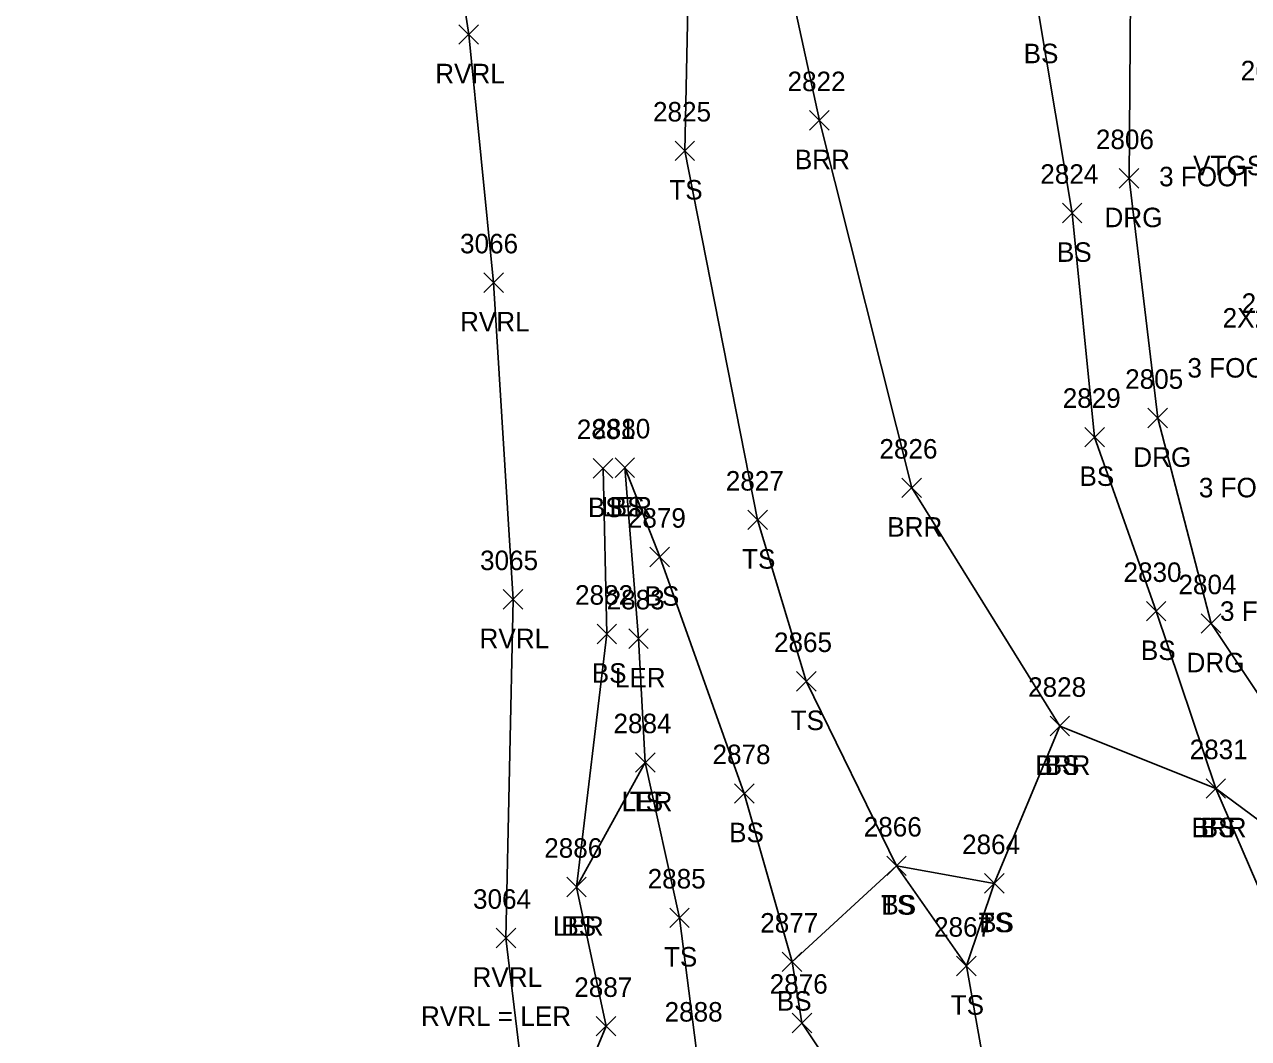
# Model space of a CAD drawing. Extents: x 1461855 to 1464118, y 556196 to 557441.
# Drawn here: x 1462198.6 to 1462324.1, y 556771.6 to 556875.5 of the extents above; entities that cross this region are included whole.
import ezdxf

# ---------------------------------------------------------------- set-up
doc = ezdxf.new("R2010")
doc.units = 0
for name, color, linetype in [('C_C', 7, 'Continuous'), ('L_A', 7, 'Continuous'), ('L_C', 7, 'Continuous'), ('L_I', 7, 'Continuous'), ('L_TIC', 7, 'Continuous'), ('LABL', 7, 'Continuous'), ('LARO', 7, 'Continuous'), ('LAWE', 7, 'Continuous'), ('LELB', 7, 'Continuous'), ('LSOGP', 7, 'Continuous'), ('R_A', 7, 'Continuous'), ('R_I', 7, 'Continuous'), ('R_TIC', 7, 'Continuous'), ('RDG', 7, 'Continuous')]:
    doc.layers.add(name, color=color, linetype=linetype)

msp = doc.modelspace()

# ---------------------------------------------------------------- linework, layer by layer
at = {"layer": 'L_TIC'}
for points in [[(1462243.13, 556873.5), (1462245.13, 556875.5)], [(1462245.13, 556873.5), (1462243.13, 556875.5)], [(1462279.07, 556864.7), (1462281.07, 556866.7)], [(1462281.07, 556864.7), (1462279.07, 556866.7)], [(1462265.28, 556861.59), (1462267.28, 556863.59)], [(1462267.28, 556861.59), (1462265.28, 556863.59)], [(1462304.98, 556855.21), (1462306.98, 556857.21)], [(1462306.98, 556855.21), (1462304.98, 556857.21)], [(1462245.68, 556848.08), (1462247.68, 556850.08)], [(1462247.68, 556848.08), (1462245.68, 556850.08)], [(1462307.29, 556832.25), (1462309.29, 556834.25)], [(1462309.29, 556832.25), (1462307.29, 556834.25)], [(1462256.9, 556829.05), (1462258.9, 556831.05)], [(1462258.9, 556829.05), (1462256.9, 556831.05)], [(1462259.14, 556829.12), (1462261.14, 556831.12)], [(1462261.14, 556829.12), (1462259.14, 556831.12)], [(1462259.14, 556829.12), (1462261.14, 556831.12)], [(1462261.14, 556829.12), (1462259.14, 556831.12)], [(1462288.54, 556827.05), (1462290.54, 556829.05)], [(1462290.54, 556827.05), (1462288.54, 556829.05)], [(1462272.74, 556823.77), (1462274.74, 556825.77)], [(1462274.74, 556823.77), (1462272.74, 556825.77)], [(1462262.71, 556819.97), (1462264.71, 556821.97)], [(1462264.71, 556819.97), (1462262.71, 556821.97)], [(1462247.67, 556815.62), (1462249.67, 556817.62)], [(1462249.67, 556815.62), (1462247.67, 556817.62)], [(1462313.59, 556814.41), (1462315.59, 556816.41)], [(1462315.59, 556814.41), (1462313.59, 556816.41)], [(1462257.29, 556812.08), (1462259.29, 556814.08)], [(1462259.29, 556812.08), (1462257.29, 556814.08)], [(1462260.53, 556811.6), (1462262.53, 556813.6)], [(1462262.53, 556811.6), (1462260.53, 556813.6)], [(1462277.73, 556807.23), (1462279.73, 556809.23)], [(1462279.73, 556807.23), (1462277.73, 556809.23)], [(1462303.73, 556802.64), (1462305.73, 556804.64)], [(1462305.73, 556802.64), (1462303.73, 556804.64)], [(1462303.73, 556802.64), (1462305.73, 556804.64)], [(1462305.73, 556802.64), (1462303.73, 556804.64)], [(1462261.23, 556798.91), (1462263.23, 556800.91)], [(1462263.23, 556798.91), (1462261.23, 556800.91)], [(1462261.23, 556798.91), (1462263.23, 556800.91)], [(1462263.23, 556798.91), (1462261.23, 556800.91)], [(1462271.38, 556795.74), (1462273.38, 556797.74)], [(1462273.38, 556795.74), (1462271.38, 556797.74)], [(1462319.72, 556796.25), (1462321.72, 556798.25)], [(1462321.72, 556796.25), (1462319.72, 556798.25)], [(1462319.72, 556796.25), (1462321.72, 556798.25)], [(1462321.72, 556796.25), (1462319.72, 556798.25)], [(1462286.98, 556788.32), (1462288.98, 556790.32)], [(1462288.98, 556788.32), (1462286.98, 556790.32)], [(1462286.98, 556788.32), (1462288.98, 556790.32)], [(1462288.98, 556788.32), (1462286.98, 556790.32)], [(1462297, 556786.52), (1462299, 556788.52)], [(1462299, 556786.52), (1462297, 556788.52)], [(1462297, 556786.52), (1462299, 556788.52)], [(1462299, 556786.52), (1462297, 556788.52)], [(1462254.18, 556786.15), (1462256.18, 556788.15)], [(1462256.18, 556786.15), (1462254.18, 556788.15)], [(1462254.18, 556786.15), (1462256.18, 556788.15)], [(1462256.18, 556786.15), (1462254.18, 556788.15)], [(1462264.73, 556783), (1462266.73, 556785)], [(1462266.73, 556783), (1462264.73, 556785)], [(1462246.95, 556780.92), (1462248.95, 556782.92)], [(1462248.95, 556780.92), (1462246.95, 556782.92)], [(1462276.27, 556778.48), (1462278.27, 556780.48)], [(1462278.27, 556778.48), (1462276.27, 556780.48)], [(1462276.27, 556778.48), (1462278.27, 556780.48)], [(1462278.27, 556778.48), (1462276.27, 556780.48)], [(1462294.14, 556778.06), (1462296.14, 556780.06)], [(1462296.14, 556778.06), (1462294.14, 556780.06)], [(1462294.14, 556778.06), (1462296.14, 556780.06)], [(1462296.14, 556778.06), (1462294.14, 556780.06)], [(1462257.21, 556771.89), (1462259.21, 556773.89)], [(1462259.21, 556771.89), (1462257.21, 556773.89)], [(1462277.29, 556772.22), (1462279.29, 556774.22)], [(1462279.29, 556772.22), (1462277.29, 556774.22)]]:
    msp.add_lwpolyline(points, dxfattribs=at)
at = {"layer": 'LABL'}
msp.add_lwpolyline([(1462266.97, 556912.47), (1462274.52, 556891.23), (1462280.07, 556865.7), (1462289.54, 556828.05), (1462304.73, 556803.64), (1462320.72, 556797.25), (1462335.19, 556786.53), (1462348.92, 556766.91), (1462363.68, 556746.45), (1462353.82, 556738.72), (1462344.08, 556725.82), (1462329.22, 556725.69), (1462313.32, 556709.65), (1462319.88, 556687.65), (1462319.87, 556671.79), (1462309.53, 556658.61)], dxfattribs=at)
at = {"layer": 'LARO'}
msp.add_lwpolyline([(1462260.14, 556830.12), (1462261.53, 556812.6), (1462262.23, 556799.91), (1462255.18, 556787.15), (1462258.21, 556772.89), (1462253.33, 556761.15), (1462259.59, 556751.32), (1462261.56, 556744.72), (1462268.34, 556742.81)], dxfattribs=at)
at = {"layer": 'LAWE'}
msp.add_lwpolyline([(1462265.23, 556618.21), (1462263.93, 556629.6), (1462266.44, 556651.26), (1462260.2, 556674.06), (1462259.87, 556695.11), (1462258.93, 556722.92), (1462256.31, 556737.03), (1462252.12, 556747.13), (1462247.95, 556781.92), (1462248.67, 556816.62), (1462246.68, 556849.08), (1462244.13, 556874.5), (1462240.34, 556899.25)], dxfattribs=at)
at = {"layer": 'LELB'}
for points in [[(1462298.79, 556927.09), (1462302.53, 556917.21), (1462305.12, 556905.68), (1462302.57, 556876.56), (1462305.98, 556856.21), (1462308.29, 556833.25), (1462314.59, 556815.41), (1462320.72, 556797.25), (1462329.01, 556778.02), (1462338.28, 556765.66), (1462353.82, 556738.72), (1462367.21, 556725.65), (1462382.15, 556699.86)], [(1462261.18, 556912.03), (1462266.82, 556888.69), (1462266.28, 556862.59), (1462273.74, 556824.77), (1462278.73, 556808.23), (1462287.98, 556789.32), (1462295.14, 556779.06)], [(1462257.9, 556830.05), (1462258.29, 556813.08), (1462255.18, 556787.15)], [(1462316.86, 556735.23), (1462303.82, 556737.87), (1462288.92, 556757.23), (1462278.29, 556773.22), (1462277.27, 556779.48), (1462272.38, 556796.74), (1462263.71, 556820.97), (1462260.14, 556830.12)], [(1462304.73, 556803.64), (1462298, 556787.52), (1462287.98, 556789.32), (1462277.27, 556779.48)], [(1462262.23, 556799.91), (1462265.73, 556784), (1462267.47, 556770.36), (1462270.72, 556756.16), (1462276.71, 556744.31), (1462292.03, 556724.85), (1462294.74, 556707.55), (1462301.08, 556685.25), (1462305.39, 556672.02), (1462305.78, 556659.19), (1462310.58, 556646.99), (1462312.81, 556626.13), (1462316.26, 556596.46)], [(1462298, 556787.52), (1462295.14, 556779.06), (1462297.93, 556763.45), (1462309.93, 556757.22), (1462315.41, 556750.42), (1462316.86, 556735.23)]]:
    msp.add_lwpolyline(points, dxfattribs=at)
at = {"layer": 'LSOGP'}
msp.add_lwpolyline([(1462240.34, 556899.25), (1462244.13, 556874.5), (1462246.68, 556849.08), (1462248.67, 556816.62), (1462247.95, 556781.92), (1462252.12, 556747.13), (1462256.31, 556737.03), (1462258.93, 556722.92), (1462259.87, 556695.11), (1462162.23, 556679.75)], dxfattribs=at)
at = {"layer": 'R_TIC'}
for points in [[(1462310.82, 556858.76), (1462312.82, 556860.76)], [(1462312.82, 556858.76), (1462310.82, 556860.76)], [(1462313.76, 556834.2), (1462315.76, 556836.2)], [(1462315.76, 556834.2), (1462313.76, 556836.2)], [(1462319.22, 556813.15), (1462321.22, 556815.15)], [(1462321.22, 556813.15), (1462319.22, 556815.15)]]:
    msp.add_lwpolyline(points, dxfattribs=at)
at = {"layer": 'RDG'}
msp.add_lwpolyline([(1462389.31, 556702.38), (1462382.82, 556722.74), (1462375.16, 556739.02), (1462362.56, 556757.38), (1462344.46, 556782.71), (1462331.9, 556796.69), (1462320.22, 556814.15), (1462314.76, 556835.2), (1462311.82, 556859.76), (1462312.08, 556892.51), (1462314.63, 556919.62), (1462308.29, 556930.67)], dxfattribs=at)

# ---------------------------------------------------------------- texts
at = {"layer": 'C_C'}
msp.add_text('VTGS STAMPED CVPS SEYMOUR 2006', height=2, dxfattribs=at).set_placement((1462318.39, 556860.08))
at = {"layer": 'L_A'}
for s, p in [('BS', (1462301.01, 556871.56)), ('RVRL', (1462240.7, 556869.5)), ('BRR', (1462277.56, 556860.7)), ('TS', (1462264.69, 556857.59)), ('BS', (1462304.42, 556851.21)), ('RVRL', (1462243.24, 556844.08)), ('BS', (1462306.73, 556828.25)), ('BS', (1462256.35, 556825.05)), ('LER', (1462257.72, 556825.12)), ('BS', (1462258.58, 556825.12)), ('BRR', (1462287.03, 556823.05)), ('TS', (1462272.15, 556819.77)), ('BS', (1462262.15, 556815.97)), ('RVRL', (1462245.24, 556811.62)), ('BS', (1462313.03, 556810.41)), ('BS', (1462256.74, 556808.08)), ('LER', (1462259.11, 556807.6)), ('TS', (1462277.13, 556803.23)), ('BRR', (1462302.21, 556798.64)), ('BS', (1462303.17, 556798.64)), ('LER', (1462259.81, 556794.91)), ('TS', (1462260.64, 556794.91)), ('BS', (1462270.82, 556791.74)), ('BRR', (1462318.21, 556792.25)), ('BS', (1462319.16, 556792.25)), ('TS', (1462286.39, 556784.32)), ('BS', (1462286.42, 556784.32)), ('LER', (1462252.77, 556782.15)), ('BS', (1462253.62, 556782.15)), ('TS', (1462296.41, 556782.52)), ('BS', (1462296.44, 556782.52)), ('TS', (1462264.14, 556779)), ('RVRL', (1462244.52, 556776.92)), ('BS', (1462275.71, 556774.48)), ('BS', (1462275.71, 556774.48)), ('TS', (1462293.54, 556774.06)), ('TS', (1462293.54, 556774.06))]:
    msp.add_text(s, height=2, dxfattribs=at).set_placement(p)
at = {"layer": 'L_C'}
for s, p in [('3 FOOT DIA. PILLAR BASE', (1462314.9, 556858.95)), ('2X2 SQ PILLAR BASE CONCRETE', (1462321.41, 556844.47)), ('3 FOOT DIA. PILLAR BASE', (1462317.8, 556839.35)), ('3 FOOT DIA. PILLAR BASE', (1462318.97, 556827.08)), ('3 FOOT DIA. PILLAR BASE', (1462321.14, 556814.42)), ('RVRL = LER', (1462239.24, 556772.92))]:
    msp.add_text(s, height=2, dxfattribs=at).set_placement(p)
at = {"layer": 'L_I'}
for s, p in [('2822', (1462276.81, 556868.7)), ('2825', (1462263.02, 556865.59)), ('2824', (1462302.72, 556859.21)), ('3066', (1462243.24, 556852.08)), ('2829', (1462305.02, 556836.25)), ('2881', (1462255.21, 556833.05)), ('2880', (1462256.79, 556833.12)), ('2880', (1462256.79, 556833.12)), ('2826', (1462286.23, 556831.05)), ('2827', (1462270.48, 556827.77)), ('2879', (1462260.44, 556823.97)), ('3065', (1462245.29, 556819.62)), ('2830', (1462311.25, 556818.41)), ('2882', (1462255.03, 556816.08)), ('2883', (1462258.27, 556815.6)), ('2865', (1462275.42, 556811.23)), ('2828', (1462301.47, 556806.64)), ('2828', (1462301.47, 556806.64)), ('2884', (1462258.97, 556802.91)), ('2884', (1462258.97, 556802.91)), ('2831', (1462318.03, 556800.25)), ('2831', (1462318.03, 556800.25)), ('2878', (1462269.12, 556799.74)), ('2866', (1462284.62, 556792.32)), ('2866', (1462284.62, 556792.32)), ('2886', (1462251.87, 556790.15)), ('2886', (1462251.87, 556790.15)), ('2864', (1462294.7, 556790.52)), ('2864', (1462294.7, 556790.52)), ('2885', (1462262.47, 556787)), ('3064', (1462244.57, 556784.92)), ('2877', (1462274.01, 556782.48)), ('2877', (1462274.01, 556782.48)), ('2867', (1462291.83, 556782.06)), ('2867', (1462291.83, 556782.06)), ('2887', (1462254.95, 556775.89)), ('2876', (1462274.98, 556776.22)), ('2888', (1462264.21, 556773.36))]:
    msp.add_text(s, height=2, dxfattribs=at).set_placement(p)
at = {"layer": 'R_A'}
for p in [(1462309.3, 556854.76), (1462312.25, 556830.2), (1462317.71, 556809.15)]:
    msp.add_text('DRG', height=2, dxfattribs=at).set_placement(p)
at = {"layer": 'R_I'}
for s, p in [('2633', (1462323.26, 556869.81)), ('2806', (1462308.42, 556862.76)), ('2634', (1462323.36, 556845.98)), ('2805', (1462311.42, 556838.2)), ('2804', (1462316.88, 556817.15))]:
    msp.add_text(s, height=2, dxfattribs=at).set_placement(p)

doc.saveas('drawing.dxf')
